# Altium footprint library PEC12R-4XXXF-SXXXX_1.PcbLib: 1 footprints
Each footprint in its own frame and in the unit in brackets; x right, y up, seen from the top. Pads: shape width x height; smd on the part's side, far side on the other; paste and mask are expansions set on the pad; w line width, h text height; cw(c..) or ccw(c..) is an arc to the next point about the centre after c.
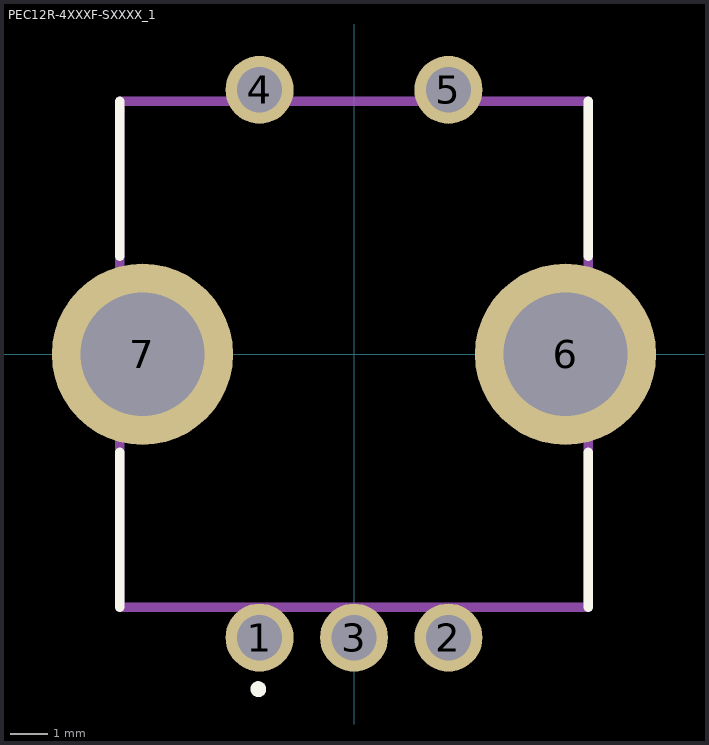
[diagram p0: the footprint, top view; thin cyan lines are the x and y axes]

## PEC12R-4XXXF-SXXXX_1 [mm]
pads (7):
  round 1.8 hole 1.2: 1(-2.5,-7.5) 2(2.5,-7.5) 3(0,-7.5) 4(-2.5,7) 5(2.5,7)
  round 4.8 hole 3.28: 6(5.6,0) 7(-5.6,0)
Top Overlay:
  circle w0.254: c-2.533,-8.863 r0.082
  lines w0.254: -6.2,-6.7 -6.2,-2.6 ; -6.2,2.6 -6.2,6.7 ; 6.2,-6.7 6.2,-2.6 ; 6.2,2.6 6.2,6.7
Mechanical 15:
  lines w0.254: -6.2,-6.7 6.2,-6.7 6.2,6.7 -6.2,6.7 -6.2,-6.7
